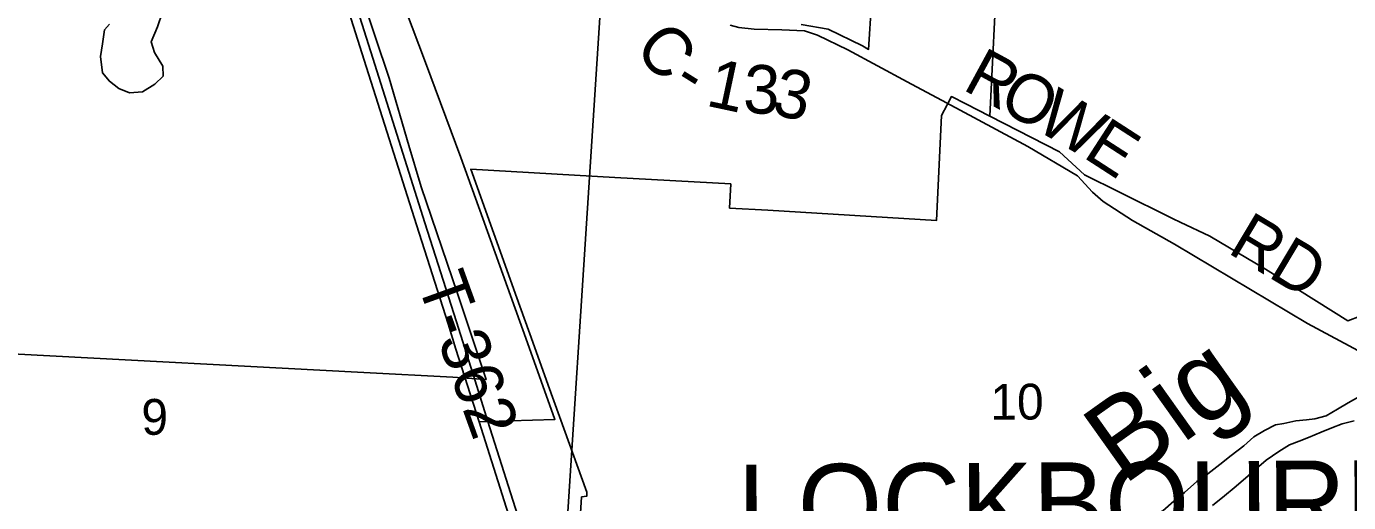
# Model space of a CAD drawing. Extents: x 114604 to 551442, y 316898 to 567001.
# Drawn here: x 204563 to 212720, y 330905 to 333844 of the extents above; entities that cross this region are included whole.
import ezdxf

# ---------------------------------------------------------------- set-up
doc = ezdxf.new("R2010")
doc.units = 0
for name, color, linetype in [('DV_X_County_Line', 7, 'Continuous'), ('GE_P_Alignment_1000_Cardinal_Points', 7, 'Continuous'), ('GE_P_Alignment_1000_Stations', 7, 'Continuous'), ('GE_P_Alignment_100_Stations', 7, 'Continuous'), ('GE_P_Alignment_500_Bearings', 7, 'Continuous'), ('MT_X_Edge_Line', 7, 'Continuous'), ('PM_P_CL_Double_Solid', 7, 'Continuous'), ('PM_P_Crosswalk', 7, 'Continuous'), ('PV_X_Curb', 7, 'Continuous'), ('RD_P_GR_Rt', 7, 'Continuous'), ('SH_Named_Boundary', 7, 'Continuous'), ('SN_P_Signs', 7, 'Continuous')]:
    doc.layers.add(name, color=color, linetype=linetype)

msp = doc.modelspace()

# ---------------------------------------------------------------- linework, layer by layer
at = {"layer": 'DV_X_County_Line'}
for points in [[(212783.2, 331557.8), (212717.5, 331521.3), (212651.9, 331480.8), (212582.2, 331440.3), (212512.4, 331421.9), (212460.5, 331415.5), (212394.6, 331409.1), (212320.8, 331392.7), (212268.9, 331384.3), (212201.2, 331349.8), (212135.5, 331311.4), (212073.9, 331254.9), (211996.3, 331196.3), (211926.8, 331139.8), (211851.2, 331083.3), (211783.6, 331034.8), (211708, 330968.2), (211642.4, 330913.7), (211574.9, 330855.3), (211511.1, 330824.8)], [(212754.2, 331409.4), (212680.4, 331390.9), (212616.6, 331366.4), (212550.8, 331340), (212473.1, 331307.5), (212415.3, 331285.1), (212355.5, 331260.7), (212289.8, 331220.2), (212212.3, 331167.7), (212152.6, 331115.2), (212085.1, 331056.7), (212013.5, 330996.2), (211953.9, 330947.7), (211880.3, 330887.2)]]:
    msp.add_lwpolyline(points, dxfattribs=at)
at = {"layer": 'GE_P_Alignment_1000_Cardinal_Points'}
msp.add_lwpolyline([(207355.6, 331404.2), (207410, 331406), (207823.6, 331419), (207653.4, 331891.5), (207379.6, 332658.3), (207243.1, 333036), (207024.6, 333621.9), (206813.4, 334185.5), (206737.5, 334385.1), (206705.3, 334476.8)], dxfattribs=at)
at = {"layer": 'GE_P_Alignment_1000_Stations'}
for points in [[(207213.2, 331853.1), (207164.1, 332007.6), (206968.6, 332618.9), (206647.4, 333635.8), (206394.1, 334435.4), (206074.1, 335447.1), (205888.6, 336034.7), (205837, 336213.3), (205811.9, 336321.9), (205791.4, 336430.7), (205773.1, 336554.5), (205767.4, 336631.4)], [(207331.2, 331655.8), (207216.3, 332020.5), (207020.8, 332631.8), (206699.6, 333648.6), (206446.3, 334448.3)], [(208096.4, 329069.6), (207988.5, 329407.6), (207355.6, 331404.2), (207213.2, 331853.1)], [(208152.2, 329067.6), (208044.4, 329405.6), (207410, 331406), (207331.2, 331655.8)]]:
    msp.add_lwpolyline(points, dxfattribs=at)
at = {"layer": 'GE_P_Alignment_100_Stations'}
for points in [[(209796.2, 334279.8), (209759.3, 333701.7), (209721.1, 333724.3), (209509.9, 333827.9), (209343.6, 333856.3)], [(212790.9, 332056.4), (212716.6, 332027), (212208.8, 332346.5), (211864.8, 332550.1), (211680.7, 332635.1), (211638.4, 332656.2), (211306.5, 332821.6), (211091.8, 332928.5), (210935.8, 333070.4), (210506.8, 333290.1), (210553.3, 334243.3)], [(206627.9, 334041.7), (206800, 333525.2), (206921.9, 333108.2), (206997.6, 332853.4), (207222.3, 332195.2), (207322.4, 331893.2), (207398.4, 331664.4), (207193.1, 331679.3), (206644.7, 331708.2), (204474.5, 331822.7)], [(207947.1, 330269.9), (207988.5, 330940.6), (208020.9, 330945.6), (208020.1, 330968.6), (207852.4, 331435.6), (207782.8, 331629.5), (207687.2, 331895.9), (207589.4, 332168.2), (207304.4, 332962.2), (208193.9, 332912.1), (208908.3, 332871.8), (208900.8, 332723.3), (209137.7, 332709.1), (210178.7, 332647), (210209.1, 333295), (210243.7, 333360.3), (210270, 333411.4), (210358.8, 333365.9), (210506.8, 333290.1), (210935.8, 333070.4), (211091.8, 332928.5), (211306.5, 332821.6), (211638.4, 332656.2), (211680.7, 332635.1), (211864.8, 332550.1), (212208.8, 332346.5), (212716.6, 332027), (212790.9, 332056.4)]]:
    msp.add_lwpolyline(points, dxfattribs=at)
at = {"layer": 'GE_P_Alignment_500_Bearings'}
for points in [[(208903.9, 333852.2), (208958, 333838.1), (209052.2, 333828.1), (209224.5, 333824), (209362.7, 333815.9), (209442.8, 333789.8), (209631.1, 333699.5), (209997.6, 333503), (210240.6, 333372.4)], [(210240.6, 333372.4), (210740.7, 333103.8), (211047.1, 332921.3), (211141.2, 332821), (211205.3, 332762.8), (211387.5, 332646.5), (211645.9, 332500.1), (212467, 332010.6), (213407.4, 331506), (213503.8, 331430), (213705.7, 331312.4)]]:
    msp.add_lwpolyline(points, dxfattribs=at)
at = {"layer": 'MT_X_Edge_Line'}
msp.add_lwpolyline([(205075.4, 333858.9), (205045.3, 333822.8), (205031.2, 333736.6), (205019.1, 333658.4), (205032.9, 333558.2), (205074.9, 333506), (205132.8, 333461.8), (205198.8, 333433.6), (205278.9, 333439.5), (205355, 333487.6), (205407.1, 333537.6), (205405.2, 333597.8), (205353.3, 333684.1), (205333.4, 333748.2), (205371.6, 333842.4), (205401.8, 333932.6)], dxfattribs=at)
at = {"layer": 'SN_P_Signs'}
for points in [[(202949.2, 334626.4), (208132.8, 334409.4), (207789.5, 329099.8), (202938, 329360.9), (202888.4, 329455.9), (202854.3, 329515.8), (202804.2, 329591.8), (202686, 329773.7)], [(208132.8, 334409.4), (213546, 334098.4), (213252.7, 328805.6), (207789.5, 329099.8)]]:
    msp.add_lwpolyline(points, close=True, dxfattribs=at)

# ---------------------------------------------------------------- texts
at = {"layer": 'PM_P_CL_Double_Solid'}
for s, height, rotation, p in [('C', 300, 313.30717, (208304, 333696.8)), ('R', 300, 331.49659, (210331.2, 333458.2)), ('-', 300, 328.0201, (208537.9, 333464.3)), ('1', 300, 347.97814, (208747.7, 333356.5)), ('3', 300, 357.25404, (208981, 333311.2)), ('3', 300, 347.43104, (209152.2, 333304.2)), ('O', 300, 331.2263, (210547.4, 333340.8)), ('W', 300, 329.66506, (210776.9, 333214.8)), ('E', 300, 327.11143, (211074, 333041.1)), ('RD', 300.02, 329.19419, (211966.3, 332451.1))]:
    msp.add_text(s, height=height, rotation=rotation, dxfattribs=at).set_placement(p)
at = {"layer": 'PM_P_Crosswalk'}
msp.add_text('T-362', height=300.02, rotation=289.82243, dxfattribs=at).set_placement((206970.9, 332264.3))
at = {"layer": 'PV_X_Curb'}
for s, height, rotation, p in [('10', 221.02, 0.41339, (210511, 331415.9)), ('9', 221, 0.41329, (205273, 331323.1))]:
    msp.add_text(s, height=height, rotation=rotation, dxfattribs=at).set_placement(p)
at = {"layer": 'RD_P_GR_Rt'}
msp.add_text('Big', height=500.11, rotation=35.4241, dxfattribs=at).set_placement((211330.4, 331007.5))
at = {"layer": 'SH_Named_Boundary'}
msp.add_text('LOCKBOURNE', height=500.04, rotation=0.41336, dxfattribs=at).set_placement((208952.3, 330639.1))

doc.saveas('drawing.dxf')
